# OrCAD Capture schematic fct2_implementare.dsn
size A
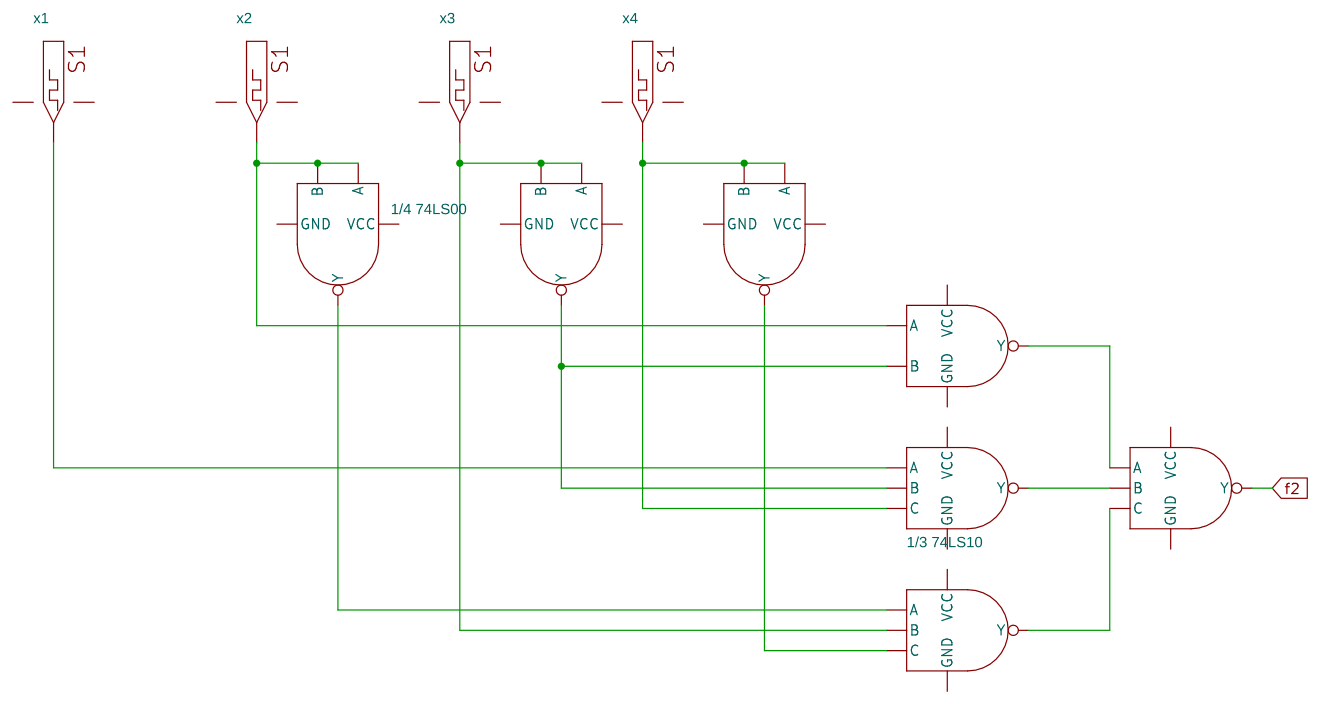
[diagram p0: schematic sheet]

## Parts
U3  1/4 74LS00  [DIP.100/14/W.300/L.800]  (section A)
U4  1/3 74LS10  [DIP.100/14/W.300/L.800]  (section A)
U5  74LS00  [DIP.100/14/W.300/L.800]  (sections A,B)
U6  74LS00  [DIP.100/14/W.300/L.800]  (section B)
U7  74LS10  [DIP.100/14/W.300/L.800]  (sections A,B)
x1  DigStim1
x2  DigStim1
x3  DigStim1
x4  DigStim1

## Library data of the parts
U3 U5 U6 = 74LS00
U4 U7 = 74LS10
x1-x4 = DigStim1

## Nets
GND: U3.7(GND) U4.7(GND) U5.7(GND) U6.7(GND) U7.7(GND) x1.3(GND) x2.3(GND) x3.3(GND) x4.3(GND)
VCC: U3.14(VCC) U4.14(VCC) U5.14(VCC) U6.14(VCC) U7.14(VCC) x1.2(VCC) x2.2(VCC) x3.2(VCC) x4.2(VCC)
f2: U7.6(Y)
N14888: U3.1(A) U3.2(B) U6.4(A) x2.OUT
N14915: U5.1(A) U5.2(B) U7.2(B) x3.OUT
N14939: U4.13(C) U5.4(A) U5.5(B) x4.OUT
N15080: U4.2(B) U5.3(Y) U6.5(B)
N15195: U4.1(A) x1.OUT
N15442: U6.6(Y) U7.3(A)
N15455: U7.5(C) U7.12(Y)
N15468: U4.12(Y) U7.4(B)
N15481: U3.3(Y) U7.1(A)
N15500: U5.6(Y) U7.13(C)
